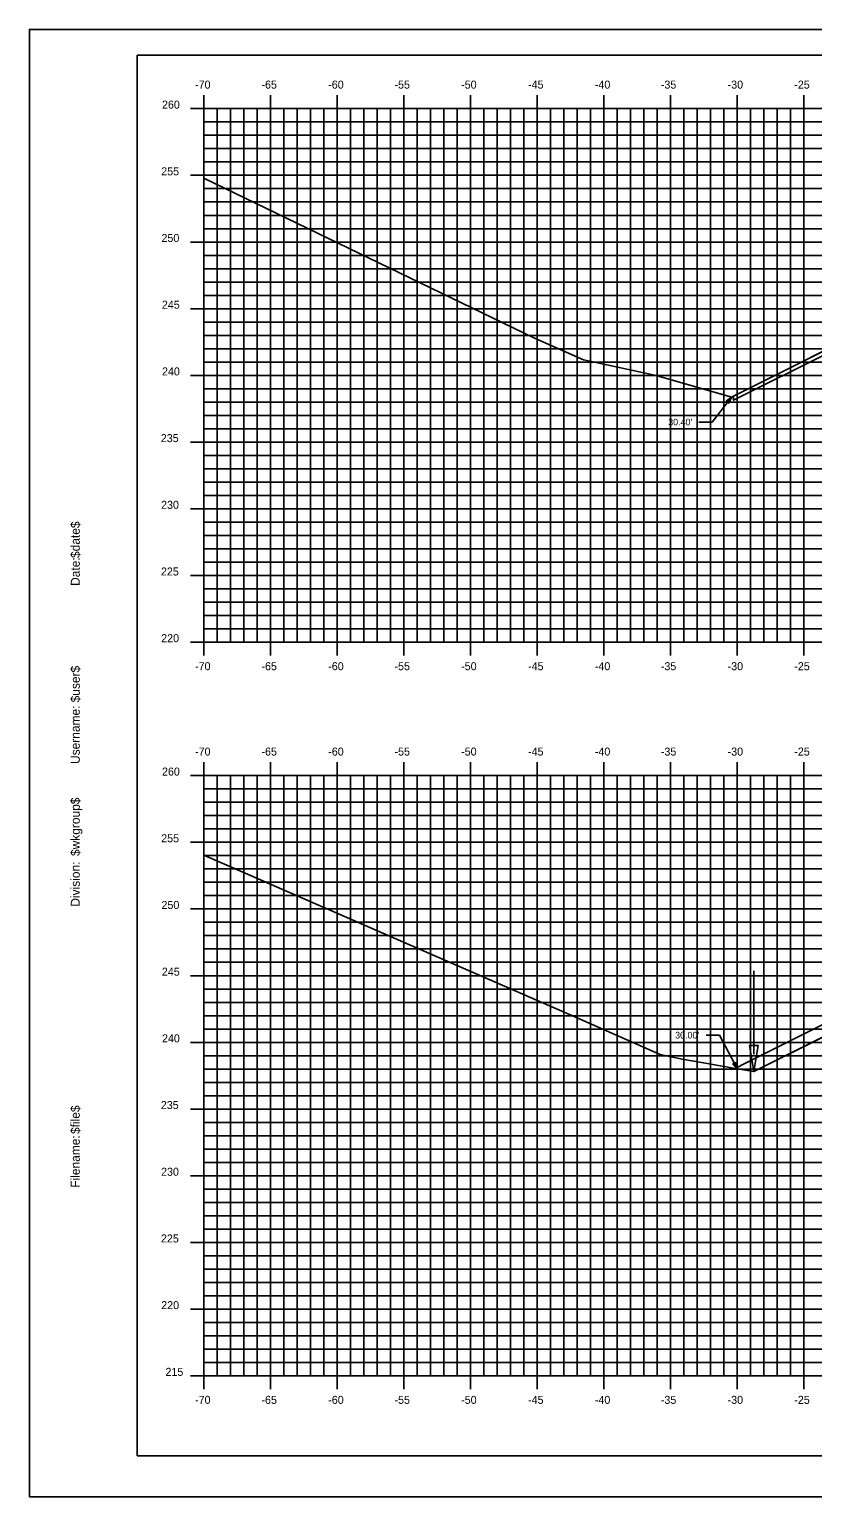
# Model space of a CAD drawing. Extents: x 1170543 to 1177585, y 609599 to 610623.
# Drawn here: x 1174608.7 to 1174667.5, y 609598.8 to 609708.8 of the extents above; entities that cross this region are included whole.
import ezdxf

# ---------------------------------------------------------------- set-up
doc = ezdxf.new("R2010")
doc.units = 0
for name, color, linetype in [('ANNOTATION', 7, 'Continuous'), ('BORDER', 7, 'Continuous'), ('D_Drainage_Ditch_Line', 7, 'Continuous'), ('D_Roadway_Centerline', 7, 'Continuous'), ('D_Roadway_SlopeLines', 7, 'Continuous'), ('H_V ANNOTATION', 7, 'Continuous'), ('MAJOR', 7, 'Continuous'), ('MINOR', 7, 'Continuous'), ('PLOT BOUNDARY', 7, 'Continuous'), ('S_Roadway_Centerline', 7, 'Continuous')]:
    doc.layers.add(name, color=color, linetype=linetype)

msp = doc.modelspace()

# ---------------------------------------------------------------- linework, layer by layer
at = {"layer": 'ANNOTATION'}
for p, q in [((1174661.38, 609681.25), (1174659.93, 609679.37)), ((1174658.93, 609679.37), (1174659.93, 609679.37)), ((1174659.47, 609633.41), (1174660.47, 609633.41)), ((1174661.84, 609630.87), (1174660.47, 609633.41))]:
    msp.add_line(p, q, dxfattribs=at)
for points in [[(1174660.98, 609680.93), (1174661.38, 609681.25), (1174661.18, 609680.78)], [(1174661.71, 609631.37), (1174661.84, 609630.87), (1174661.49, 609631.25)]]:
    msp.add_lwpolyline(points, close=True, dxfattribs=at)
at = {"layer": 'BORDER'}
for p, q in [((1174776.8, 609706.87), (1174616.8, 609706.87)), ((1174616.8, 609706.87), (1174616.8, 609601.87)), ((1174616.8, 609601.87), (1174776.8, 609601.87))]:
    msp.add_line(p, q, dxfattribs=at)
at = {"layer": 'D_Drainage_Ditch_Line'}
msp.add_line((1174663.05, 609631.99), (1174663.05, 609638.23), dxfattribs=at)
msp.add_lwpolyline([(1174662.72, 609632.64), (1174663.38, 609632.64), (1174663.05, 609630.68)], close=True, dxfattribs=at)
at = {"layer": 'D_Roadway_Centerline'}
for points in [[(1174661.38, 609681.25), (1174661.72, 609681.42), (1174667.73, 609684.42), (1174672.8, 609686.96), (1174675.8, 609687.08), (1174691.8, 609687.72), (1174707.8, 609688.36), (1174710.8, 609688.3), (1174714.79, 609686.31), (1174721.88, 609682.76), (1174735.38, 609676.01)], [(1174663.05, 609630.68), (1174667.73, 609633.01), (1174672.8, 609635.55), (1174675.8, 609635.67), (1174691.8, 609636.31), (1174707.8, 609636.95), (1174710.8, 609636.89), (1174714.79, 609634.9), (1174721.88, 609631.35), (1174729.24, 609627.67)]]:
    msp.add_lwpolyline(points, dxfattribs=at)
at = {"layer": 'D_Roadway_SlopeLines'}
msp.add_line((1174661.65, 609630.92), (1174663.05, 609630.68), dxfattribs=at)
for points in [[(1174672.8, 609686.96), (1174661.72, 609681.42)], [(1174661.72, 609681.42), (1174661.38, 609681.25)], [(1174672.8, 609635.55), (1174663.05, 609630.68)]]:
    msp.add_lwpolyline(points, dxfattribs=at)
at = {"layer": 'MAJOR'}
for p, q in [((1174621.8, 609703.87), (1174621.8, 609702.87)), ((1174626.8, 609703.87), (1174626.8, 609702.87)), ((1174631.8, 609703.87), (1174631.8, 609702.87)), ((1174636.8, 609703.87), (1174636.8, 609702.87)), ((1174641.8, 609703.87), (1174641.8, 609702.87)), ((1174646.8, 609703.87), (1174646.8, 609702.87)), ((1174651.8, 609703.87), (1174651.8, 609702.87)), ((1174656.8, 609703.87), (1174656.8, 609702.87)), ((1174661.8, 609703.87), (1174661.8, 609702.87)), ((1174666.8, 609703.87), (1174666.8, 609702.87)), ((1174620.8, 609702.87), (1174621.8, 609702.87)), ((1174621.8, 609702.87), (1174761.8, 609702.87)), ((1174621.8, 609662.87), (1174621.8, 609702.87)), ((1174621.8, 609662.87), (1174621.8, 609702.87)), ((1174621.8, 609702.87), (1174761.8, 609702.87)), ((1174626.8, 609662.87), (1174626.8, 609702.87)), ((1174631.8, 609662.87), (1174631.8, 609702.87)), ((1174636.8, 609662.87), (1174636.8, 609702.87)), ((1174641.8, 609662.87), (1174641.8, 609702.87)), ((1174646.8, 609662.87), (1174646.8, 609702.87)), ((1174651.8, 609662.87), (1174651.8, 609702.87)), ((1174656.8, 609662.87), (1174656.8, 609702.87)), ((1174661.8, 609662.87), (1174661.8, 609702.87)), ((1174666.8, 609662.87), (1174666.8, 609702.87)), ((1174620.8, 609697.87), (1174621.8, 609697.87)), ((1174621.8, 609697.87), (1174761.8, 609697.87)), ((1174620.8, 609692.87), (1174621.8, 609692.87)), ((1174621.8, 609692.87), (1174761.8, 609692.87)), ((1174620.8, 609687.87), (1174621.8, 609687.87)), ((1174621.8, 609687.87), (1174761.8, 609687.87)), ((1174620.8, 609682.87), (1174621.8, 609682.87)), ((1174621.8, 609682.87), (1174761.8, 609682.87)), ((1174620.8, 609677.87), (1174621.8, 609677.87)), ((1174621.8, 609677.87), (1174761.8, 609677.87)), ((1174620.8, 609672.87), (1174621.8, 609672.87)), ((1174621.8, 609672.87), (1174761.8, 609672.87)), ((1174620.8, 609667.87), (1174621.8, 609667.87)), ((1174621.8, 609667.87), (1174761.8, 609667.87)), ((1174620.8, 609662.87), (1174621.8, 609662.87)), ((1174621.8, 609662.87), (1174761.8, 609662.87)), ((1174621.8, 609662.87), (1174761.8, 609662.87)), ((1174621.8, 609661.87), (1174621.8, 609662.87)), ((1174626.8, 609661.87), (1174626.8, 609662.87)), ((1174631.8, 609661.87), (1174631.8, 609662.87)), ((1174636.8, 609661.87), (1174636.8, 609662.87)), ((1174641.8, 609661.87), (1174641.8, 609662.87)), ((1174646.8, 609661.87), (1174646.8, 609662.87)), ((1174651.8, 609661.87), (1174651.8, 609662.87)), ((1174656.8, 609661.87), (1174656.8, 609662.87)), ((1174661.8, 609661.87), (1174661.8, 609662.87)), ((1174666.8, 609661.87), (1174666.8, 609662.87)), ((1174621.8, 609653.87), (1174621.8, 609652.87)), ((1174626.8, 609653.87), (1174626.8, 609652.87)), ((1174631.8, 609653.87), (1174631.8, 609652.87)), ((1174636.8, 609653.87), (1174636.8, 609652.87)), ((1174641.8, 609653.87), (1174641.8, 609652.87)), ((1174646.8, 609653.87), (1174646.8, 609652.87)), ((1174651.8, 609653.87), (1174651.8, 609652.87)), ((1174656.8, 609653.87), (1174656.8, 609652.87)), ((1174661.8, 609653.87), (1174661.8, 609652.87)), ((1174666.8, 609653.87), (1174666.8, 609652.87)), ((1174620.8, 609652.87), (1174621.8, 609652.87)), ((1174621.8, 609652.87), (1174761.8, 609652.87)), ((1174621.8, 609607.87), (1174621.8, 609652.87)), ((1174621.8, 609607.87), (1174621.8, 609652.87)), ((1174621.8, 609652.87), (1174761.8, 609652.87)), ((1174626.8, 609607.87), (1174626.8, 609652.87)), ((1174631.8, 609607.87), (1174631.8, 609652.87)), ((1174636.8, 609607.87), (1174636.8, 609652.87)), ((1174641.8, 609607.87), (1174641.8, 609652.87)), ((1174646.8, 609607.87), (1174646.8, 609652.87)), ((1174651.8, 609607.87), (1174651.8, 609652.87)), ((1174656.8, 609607.87), (1174656.8, 609652.87)), ((1174661.8, 609607.87), (1174661.8, 609652.87)), ((1174666.8, 609607.87), (1174666.8, 609652.87)), ((1174620.8, 609647.87), (1174621.8, 609647.87)), ((1174621.8, 609647.87), (1174761.8, 609647.87)), ((1174620.8, 609642.87), (1174621.8, 609642.87)), ((1174621.8, 609642.87), (1174761.8, 609642.87)), ((1174620.8, 609637.87), (1174621.8, 609637.87)), ((1174621.8, 609637.87), (1174761.8, 609637.87)), ((1174620.8, 609632.87), (1174621.8, 609632.87)), ((1174621.8, 609632.87), (1174761.8, 609632.87)), ((1174620.8, 609627.87), (1174621.8, 609627.87)), ((1174621.8, 609627.87), (1174761.8, 609627.87)), ((1174620.8, 609622.87), (1174621.8, 609622.87)), ((1174621.8, 609622.87), (1174761.8, 609622.87)), ((1174620.8, 609617.87), (1174621.8, 609617.87)), ((1174621.8, 609617.87), (1174761.8, 609617.87)), ((1174620.8, 609612.87), (1174621.8, 609612.87)), ((1174621.8, 609612.87), (1174761.8, 609612.87)), ((1174620.8, 609607.87), (1174621.8, 609607.87)), ((1174621.8, 609607.87), (1174761.8, 609607.87)), ((1174621.8, 609607.87), (1174761.8, 609607.87)), ((1174621.8, 609606.87), (1174621.8, 609607.87)), ((1174626.8, 609606.87), (1174626.8, 609607.87)), ((1174631.8, 609606.87), (1174631.8, 609607.87)), ((1174636.8, 609606.87), (1174636.8, 609607.87)), ((1174641.8, 609606.87), (1174641.8, 609607.87)), ((1174646.8, 609606.87), (1174646.8, 609607.87)), ((1174651.8, 609606.87), (1174651.8, 609607.87)), ((1174656.8, 609606.87), (1174656.8, 609607.87)), ((1174661.8, 609606.87), (1174661.8, 609607.87)), ((1174666.8, 609606.87), (1174666.8, 609607.87))]:
    msp.add_line(p, q, dxfattribs=at)
at = {"layer": 'MINOR'}
for p, q in [((1174622.8, 609662.87), (1174622.8, 609702.87)), ((1174623.8, 609662.87), (1174623.8, 609702.87)), ((1174624.8, 609662.87), (1174624.8, 609702.87)), ((1174625.8, 609662.87), (1174625.8, 609702.87)), ((1174627.8, 609662.87), (1174627.8, 609702.87)), ((1174628.8, 609662.87), (1174628.8, 609702.87)), ((1174629.8, 609662.87), (1174629.8, 609702.87)), ((1174630.8, 609662.87), (1174630.8, 609702.87)), ((1174632.8, 609662.87), (1174632.8, 609702.87)), ((1174633.8, 609662.87), (1174633.8, 609702.87)), ((1174634.8, 609662.87), (1174634.8, 609702.87)), ((1174635.8, 609662.87), (1174635.8, 609702.87)), ((1174637.8, 609662.87), (1174637.8, 609702.87)), ((1174638.8, 609662.87), (1174638.8, 609702.87)), ((1174639.8, 609662.87), (1174639.8, 609702.87)), ((1174640.8, 609662.87), (1174640.8, 609702.87)), ((1174642.8, 609662.87), (1174642.8, 609702.87)), ((1174643.8, 609662.87), (1174643.8, 609702.87)), ((1174644.8, 609662.87), (1174644.8, 609702.87)), ((1174645.8, 609662.87), (1174645.8, 609702.87)), ((1174647.8, 609662.87), (1174647.8, 609702.87)), ((1174648.8, 609662.87), (1174648.8, 609702.87)), ((1174649.8, 609662.87), (1174649.8, 609702.87)), ((1174650.8, 609662.87), (1174650.8, 609702.87)), ((1174652.8, 609662.87), (1174652.8, 609702.87)), ((1174653.8, 609662.87), (1174653.8, 609702.87)), ((1174654.8, 609662.87), (1174654.8, 609702.87)), ((1174655.8, 609662.87), (1174655.8, 609702.87)), ((1174657.8, 609662.87), (1174657.8, 609702.87)), ((1174658.8, 609662.87), (1174658.8, 609702.87)), ((1174659.8, 609662.87), (1174659.8, 609702.87)), ((1174660.8, 609662.87), (1174660.8, 609702.87)), ((1174662.8, 609662.87), (1174662.8, 609702.87)), ((1174663.8, 609662.87), (1174663.8, 609702.87)), ((1174664.8, 609662.87), (1174664.8, 609702.87)), ((1174665.8, 609662.87), (1174665.8, 609702.87)), ((1174621.8, 609701.87), (1174761.8, 609701.87)), ((1174621.8, 609701.87), (1174622.8, 609701.87)), ((1174621.8, 609700.87), (1174761.8, 609700.87)), ((1174621.8, 609700.87), (1174622.8, 609700.87)), ((1174621.8, 609699.87), (1174761.8, 609699.87)), ((1174621.8, 609699.87), (1174622.8, 609699.87)), ((1174621.8, 609698.87), (1174761.8, 609698.87)), ((1174621.8, 609698.87), (1174622.8, 609698.87)), ((1174621.8, 609696.87), (1174761.8, 609696.87)), ((1174621.8, 609696.87), (1174622.8, 609696.87)), ((1174621.8, 609695.87), (1174761.8, 609695.87)), ((1174621.8, 609695.87), (1174622.8, 609695.87)), ((1174621.8, 609694.87), (1174761.8, 609694.87)), ((1174621.8, 609694.87), (1174622.8, 609694.87)), ((1174621.8, 609693.87), (1174761.8, 609693.87)), ((1174621.8, 609693.87), (1174622.8, 609693.87)), ((1174621.8, 609691.87), (1174761.8, 609691.87)), ((1174621.8, 609691.87), (1174622.8, 609691.87)), ((1174621.8, 609690.87), (1174761.8, 609690.87)), ((1174621.8, 609690.87), (1174622.8, 609690.87)), ((1174621.8, 609689.87), (1174761.8, 609689.87)), ((1174621.8, 609689.87), (1174622.8, 609689.87)), ((1174621.8, 609688.87), (1174761.8, 609688.87)), ((1174621.8, 609688.87), (1174622.8, 609688.87)), ((1174621.8, 609686.87), (1174761.8, 609686.87)), ((1174621.8, 609686.87), (1174622.8, 609686.87)), ((1174621.8, 609685.87), (1174761.8, 609685.87)), ((1174621.8, 609685.87), (1174622.8, 609685.87)), ((1174621.8, 609684.87), (1174761.8, 609684.87)), ((1174621.8, 609684.87), (1174622.8, 609684.87)), ((1174621.8, 609683.87), (1174761.8, 609683.87)), ((1174621.8, 609683.87), (1174622.8, 609683.87)), ((1174621.8, 609681.87), (1174761.8, 609681.87)), ((1174621.8, 609681.87), (1174622.8, 609681.87)), ((1174621.8, 609680.87), (1174761.8, 609680.87)), ((1174621.8, 609680.87), (1174622.8, 609680.87)), ((1174621.8, 609679.87), (1174761.8, 609679.87)), ((1174621.8, 609679.87), (1174622.8, 609679.87)), ((1174621.8, 609678.87), (1174761.8, 609678.87)), ((1174621.8, 609678.87), (1174622.8, 609678.87)), ((1174621.8, 609676.87), (1174761.8, 609676.87)), ((1174621.8, 609676.87), (1174622.8, 609676.87)), ((1174621.8, 609675.87), (1174761.8, 609675.87)), ((1174621.8, 609675.87), (1174622.8, 609675.87)), ((1174621.8, 609674.87), (1174761.8, 609674.87)), ((1174621.8, 609674.87), (1174622.8, 609674.87)), ((1174621.8, 609673.87), (1174761.8, 609673.87)), ((1174621.8, 609673.87), (1174622.8, 609673.87)), ((1174621.8, 609671.87), (1174761.8, 609671.87)), ((1174621.8, 609671.87), (1174622.8, 609671.87)), ((1174621.8, 609670.87), (1174761.8, 609670.87)), ((1174621.8, 609670.87), (1174622.8, 609670.87)), ((1174621.8, 609669.87), (1174761.8, 609669.87)), ((1174621.8, 609669.87), (1174622.8, 609669.87)), ((1174621.8, 609668.87), (1174761.8, 609668.87)), ((1174621.8, 609668.87), (1174622.8, 609668.87)), ((1174621.8, 609666.87), (1174761.8, 609666.87)), ((1174621.8, 609666.87), (1174622.8, 609666.87)), ((1174621.8, 609665.87), (1174761.8, 609665.87)), ((1174621.8, 609665.87), (1174622.8, 609665.87)), ((1174621.8, 609664.87), (1174761.8, 609664.87)), ((1174621.8, 609664.87), (1174622.8, 609664.87)), ((1174621.8, 609663.87), (1174761.8, 609663.87)), ((1174621.8, 609663.87), (1174622.8, 609663.87)), ((1174622.8, 609607.87), (1174622.8, 609652.87)), ((1174623.8, 609607.87), (1174623.8, 609652.87)), ((1174624.8, 609607.87), (1174624.8, 609652.87)), ((1174625.8, 609607.87), (1174625.8, 609652.87)), ((1174627.8, 609607.87), (1174627.8, 609652.87)), ((1174628.8, 609607.87), (1174628.8, 609652.87)), ((1174629.8, 609607.87), (1174629.8, 609652.87)), ((1174630.8, 609607.87), (1174630.8, 609652.87)), ((1174632.8, 609607.87), (1174632.8, 609652.87)), ((1174633.8, 609607.87), (1174633.8, 609652.87)), ((1174634.8, 609607.87), (1174634.8, 609652.87)), ((1174635.8, 609607.87), (1174635.8, 609652.87)), ((1174637.8, 609607.87), (1174637.8, 609652.87)), ((1174638.8, 609607.87), (1174638.8, 609652.87)), ((1174639.8, 609607.87), (1174639.8, 609652.87)), ((1174640.8, 609607.87), (1174640.8, 609652.87)), ((1174642.8, 609607.87), (1174642.8, 609652.87)), ((1174643.8, 609607.87), (1174643.8, 609652.87)), ((1174644.8, 609607.87), (1174644.8, 609652.87)), ((1174645.8, 609607.87), (1174645.8, 609652.87)), ((1174647.8, 609607.87), (1174647.8, 609652.87)), ((1174648.8, 609607.87), (1174648.8, 609652.87)), ((1174649.8, 609607.87), (1174649.8, 609652.87)), ((1174650.8, 609607.87), (1174650.8, 609652.87)), ((1174652.8, 609607.87), (1174652.8, 609652.87)), ((1174653.8, 609607.87), (1174653.8, 609652.87)), ((1174654.8, 609607.87), (1174654.8, 609652.87)), ((1174655.8, 609607.87), (1174655.8, 609652.87)), ((1174657.8, 609607.87), (1174657.8, 609652.87)), ((1174658.8, 609607.87), (1174658.8, 609652.87)), ((1174659.8, 609607.87), (1174659.8, 609652.87)), ((1174660.8, 609607.87), (1174660.8, 609652.87)), ((1174662.8, 609607.87), (1174662.8, 609652.87)), ((1174663.8, 609607.87), (1174663.8, 609652.87)), ((1174664.8, 609607.87), (1174664.8, 609652.87)), ((1174665.8, 609607.87), (1174665.8, 609652.87)), ((1174621.8, 609651.87), (1174761.8, 609651.87)), ((1174621.8, 609651.87), (1174622.8, 609651.87)), ((1174621.8, 609650.87), (1174761.8, 609650.87)), ((1174621.8, 609650.87), (1174622.8, 609650.87)), ((1174621.8, 609649.87), (1174761.8, 609649.87)), ((1174621.8, 609649.87), (1174622.8, 609649.87)), ((1174621.8, 609648.87), (1174761.8, 609648.87)), ((1174621.8, 609648.87), (1174622.8, 609648.87)), ((1174621.8, 609646.87), (1174761.8, 609646.87)), ((1174621.8, 609646.87), (1174622.8, 609646.87)), ((1174621.8, 609645.87), (1174761.8, 609645.87)), ((1174621.8, 609645.87), (1174622.8, 609645.87)), ((1174621.8, 609644.87), (1174761.8, 609644.87)), ((1174621.8, 609644.87), (1174622.8, 609644.87)), ((1174621.8, 609643.87), (1174761.8, 609643.87)), ((1174621.8, 609643.87), (1174622.8, 609643.87)), ((1174621.8, 609641.87), (1174761.8, 609641.87)), ((1174621.8, 609641.87), (1174622.8, 609641.87)), ((1174621.8, 609640.87), (1174761.8, 609640.87)), ((1174621.8, 609640.87), (1174622.8, 609640.87)), ((1174621.8, 609639.87), (1174761.8, 609639.87)), ((1174621.8, 609639.87), (1174622.8, 609639.87)), ((1174621.8, 609638.87), (1174761.8, 609638.87)), ((1174621.8, 609638.87), (1174622.8, 609638.87)), ((1174621.8, 609636.87), (1174761.8, 609636.87)), ((1174621.8, 609636.87), (1174622.8, 609636.87)), ((1174621.8, 609635.87), (1174761.8, 609635.87)), ((1174621.8, 609635.87), (1174622.8, 609635.87)), ((1174621.8, 609634.87), (1174761.8, 609634.87)), ((1174621.8, 609634.87), (1174622.8, 609634.87)), ((1174621.8, 609633.87), (1174761.8, 609633.87)), ((1174621.8, 609633.87), (1174622.8, 609633.87)), ((1174621.8, 609631.87), (1174761.8, 609631.87)), ((1174621.8, 609631.87), (1174622.8, 609631.87)), ((1174621.8, 609630.87), (1174761.8, 609630.87)), ((1174621.8, 609630.87), (1174622.8, 609630.87)), ((1174621.8, 609629.87), (1174761.8, 609629.87)), ((1174621.8, 609629.87), (1174622.8, 609629.87)), ((1174621.8, 609628.87), (1174761.8, 609628.87)), ((1174621.8, 609628.87), (1174622.8, 609628.87)), ((1174621.8, 609626.87), (1174761.8, 609626.87)), ((1174621.8, 609626.87), (1174622.8, 609626.87)), ((1174621.8, 609625.87), (1174761.8, 609625.87)), ((1174621.8, 609625.87), (1174622.8, 609625.87)), ((1174621.8, 609624.87), (1174761.8, 609624.87)), ((1174621.8, 609624.87), (1174622.8, 609624.87)), ((1174621.8, 609623.87), (1174761.8, 609623.87)), ((1174621.8, 609623.87), (1174622.8, 609623.87)), ((1174621.8, 609621.87), (1174761.8, 609621.87)), ((1174621.8, 609621.87), (1174622.8, 609621.87)), ((1174621.8, 609620.87), (1174761.8, 609620.87)), ((1174621.8, 609620.87), (1174622.8, 609620.87)), ((1174621.8, 609619.87), (1174761.8, 609619.87)), ((1174621.8, 609619.87), (1174622.8, 609619.87)), ((1174621.8, 609618.87), (1174761.8, 609618.87)), ((1174621.8, 609618.87), (1174622.8, 609618.87)), ((1174621.8, 609616.87), (1174761.8, 609616.87)), ((1174621.8, 609616.87), (1174622.8, 609616.87)), ((1174621.8, 609615.87), (1174761.8, 609615.87)), ((1174621.8, 609615.87), (1174622.8, 609615.87)), ((1174621.8, 609614.87), (1174761.8, 609614.87)), ((1174621.8, 609614.87), (1174622.8, 609614.87)), ((1174621.8, 609613.87), (1174761.8, 609613.87)), ((1174621.8, 609613.87), (1174622.8, 609613.87)), ((1174621.8, 609611.87), (1174761.8, 609611.87)), ((1174621.8, 609611.87), (1174622.8, 609611.87)), ((1174621.8, 609610.87), (1174761.8, 609610.87)), ((1174621.8, 609610.87), (1174622.8, 609610.87)), ((1174621.8, 609609.87), (1174761.8, 609609.87)), ((1174621.8, 609609.87), (1174622.8, 609609.87)), ((1174621.8, 609608.87), (1174761.8, 609608.87)), ((1174621.8, 609608.87), (1174622.8, 609608.87))]:
    msp.add_line(p, q, dxfattribs=at)
at = {"layer": 'PLOT BOUNDARY'}
msp.add_lwpolyline([(1174608.71, 609598.81), (1174778.71, 609598.81), (1174778.71, 609708.81), (1174608.71, 609708.81)], close=True, dxfattribs=at)
at = {"layer": 'S_Roadway_Centerline'}
for points in [[(1174621.8, 609697.65), (1174646.54, 609685.69), (1174650.29, 609684.03), (1174650.75, 609683.93), (1174655.73, 609682.86), (1174661.49, 609681.22), (1174661.52, 609681.21), (1174661.54, 609681.01), (1174661.54, 609681.01), (1174664.89, 609682.69), (1174664.92, 609682.71), (1174665.25, 609682.87), (1174673.35, 609686.92)], [(1174621.8, 609646.9), (1174649.22, 609634.97), (1174656.03, 609631.95), (1174657.67, 609631.6), (1174659.28, 609631.34), (1174661.65, 609630.92), (1174662.49, 609631.34), (1174670.77, 609635.49)]]:
    msp.add_lwpolyline(points, dxfattribs=at)

# ---------------------------------------------------------------- texts
at = {"layer": 'ANNOTATION'}
for s, p in [("30.40'", (1174656.63, 609679.12)), ("30.00'", (1174657.15, 609633.16))]:
    msp.add_text(s, height=0.5, dxfattribs=at).set_placement(p)
at = {"layer": 'BORDER'}
for s, p in [('$date$', (1174612.49, 609669.18)), ('Date:', (1174612.49, 609667.09)), ('$user$', (1174612.49, 609658.36)), ('Username:', (1174612.49, 609653.74)), ('$wkgroup$', (1174612.49, 609646.84)), ('Division:', (1174612.49, 609643.04)), ('$file$', (1174612.49, 609626)), ('Filename:', (1174612.49, 609621.97))]:
    msp.add_text(s, height=0.67, rotation=90, dxfattribs=at).set_placement(p)
at = {"layer": 'H_V ANNOTATION'}
for s, p in [('-70', (1174621.14, 609704.37)), ('-65', (1174626.12, 609704.37)), ('-60', (1174631.13, 609704.37)), ('-55', (1174636.1, 609704.37)), ('-50', (1174641.1, 609704.37)), ('-45', (1174646.12, 609704.37)), ('-40', (1174651.13, 609704.37)), ('-35', (1174656.08, 609704.37)), ('-30', (1174661.09, 609704.37)), ('-25', (1174666.09, 609704.37)), ('260', (1174618.66, 609702.87)), ('255', (1174618.6, 609697.87)), ('250', (1174618.62, 609692.87)), ('245', (1174618.65, 609687.87)), ('240', (1174618.66, 609682.87)), ('235', (1174618.57, 609677.87)), ('230', (1174618.59, 609672.87)), ('225', (1174618.58, 609667.87)), ('220', (1174618.6, 609662.87)), ('-70', (1174621.14, 609660.77)), ('-65', (1174626.12, 609660.77)), ('-60', (1174631.13, 609660.77)), ('-55', (1174636.1, 609660.77)), ('-50', (1174641.1, 609660.77)), ('-45', (1174646.12, 609660.77)), ('-40', (1174651.13, 609660.77)), ('-35', (1174656.08, 609660.77)), ('-30', (1174661.09, 609660.77)), ('-25', (1174666.09, 609660.77)), ('-70', (1174621.14, 609654.37)), ('-65', (1174626.12, 609654.37)), ('-60', (1174631.13, 609654.37)), ('-55', (1174636.1, 609654.37)), ('-50', (1174641.1, 609654.37)), ('-45', (1174646.12, 609654.37)), ('-40', (1174651.13, 609654.37)), ('-35', (1174656.08, 609654.37)), ('-30', (1174661.09, 609654.37)), ('-25', (1174666.09, 609654.37)), ('260', (1174618.66, 609652.87)), ('255', (1174618.6, 609647.87)), ('250', (1174618.62, 609642.87)), ('245', (1174618.65, 609637.87)), ('240', (1174618.66, 609632.87)), ('235', (1174618.57, 609627.87)), ('230', (1174618.59, 609622.87)), ('225', (1174618.58, 609617.87)), ('220', (1174618.6, 609612.87)), ('215', (1174618.92, 609607.87)), ('-70', (1174621.14, 609605.77)), ('-65', (1174626.12, 609605.77)), ('-60', (1174631.13, 609605.77)), ('-55', (1174636.1, 609605.77)), ('-50', (1174641.1, 609605.77)), ('-45', (1174646.12, 609605.77)), ('-40', (1174651.13, 609605.77)), ('-35', (1174656.08, 609605.77)), ('-30', (1174661.09, 609605.77)), ('-25', (1174666.09, 609605.77))]:
    msp.add_text(s, height=0.6, dxfattribs=at).set_placement(p)

doc.saveas('drawing.dxf')
